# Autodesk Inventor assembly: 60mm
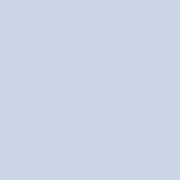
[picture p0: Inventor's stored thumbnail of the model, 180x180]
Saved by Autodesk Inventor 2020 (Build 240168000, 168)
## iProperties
Created: 2020-11
Part Number: 60mm
Document SubType Name: Assembly
Designer: Yolande
Author: Yolande
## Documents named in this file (1)
- D:\Drawing Division\3. Revit Family Files\2. Kraft\60mm.iam
